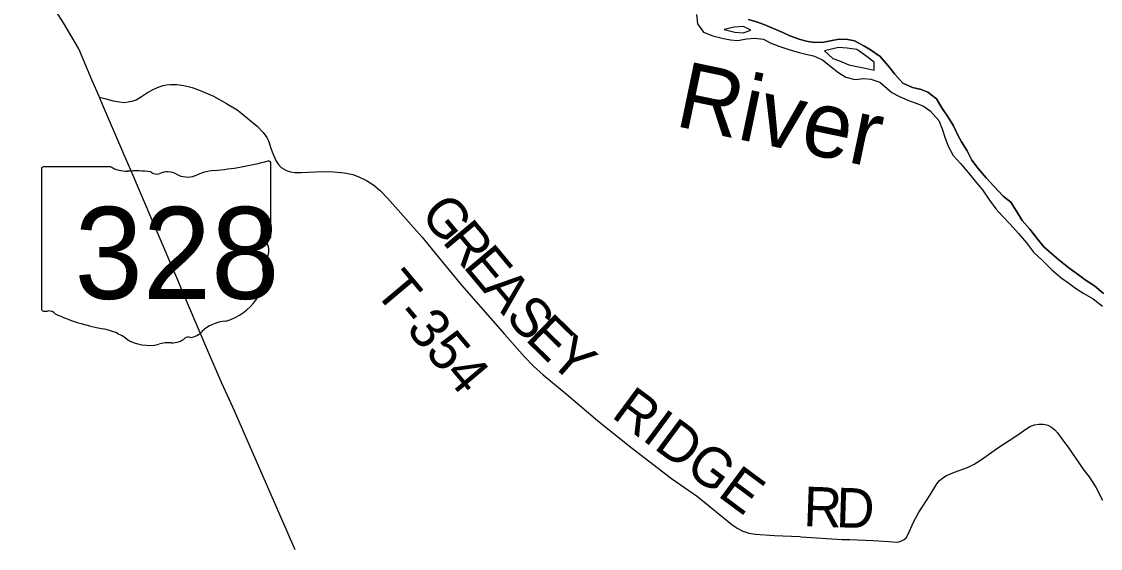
# Model space of a CAD drawing. Extents: x 0 to 34, y 0 to 22.
# Drawn here: x 4.986 to 6.535, y 19.405 to 20.161 of the extents above; entities that cross this region are included whole.
import ezdxf

# ---------------------------------------------------------------- set-up
doc = ezdxf.new("R2010")
doc.units = 0
for name, color, linetype in [('GM_X_Major_River', 7, 'Continuous'), ('GM_X_Major_River_Text', 7, 'Continuous'), ('GM_X_State_Location', 7, 'Continuous'), ('GM_X_State_Route', 7, 'Continuous'), ('GM_X_State_Shield', 7, 'Continuous'), ('GM_X_Township_Road', 7, 'Continuous'), ('GM_X_Township_Road_Text', 7, 'Continuous')]:
    doc.layers.add(name, color=color, linetype=linetype)

msp = doc.modelspace()

# ---------------------------------------------------------------- linework, layer by layer
at = {"layer": 'GM_X_Major_River'}
for p, q in [((5.9547, 20.1708), (5.9559, 20.1575)), ((5.9559, 20.1575), (5.9647, 20.1455)), ((6.0086, 20.1527), (5.9943, 20.1493)), ((6.0218, 20.1536), (6.0086, 20.1527)), ((6.0251, 20.152), (6.0218, 20.1536)), ((6.0328, 20.1484), (6.0251, 20.152)), ((6.0407, 20.1602), (6.0293, 20.1639)), ((6.0528, 20.1561), (6.0407, 20.1602)), ((6.0786, 20.145), (6.0528, 20.1561)), ((5.9647, 20.1455), (5.978, 20.1403)), ((5.978, 20.1403), (5.9936, 20.1366)), ((5.9936, 20.1366), (6.0034, 20.1344)), ((5.9943, 20.1493), (6.0098, 20.1455)), ((6.0034, 20.1344), (6.0137, 20.1338)), ((6.0098, 20.1455), (6.0215, 20.1445)), ((6.0137, 20.1338), (6.0269, 20.1362)), ((6.0215, 20.1445), (6.0328, 20.1484)), ((6.0269, 20.1362), (6.0378, 20.137)), ((6.0378, 20.137), (6.0507, 20.1353)), ((6.0507, 20.1353), (6.0606, 20.13)), ((6.0885, 20.1405), (6.0786, 20.145)), ((6.1022, 20.1357), (6.0885, 20.1405)), ((6.112, 20.1324), (6.1022, 20.1357)), ((6.1593, 20.1355), (6.1495, 20.1335)), ((6.1718, 20.1352), (6.1593, 20.1355)), ((6.1813, 20.133), (6.1718, 20.1352)), ((6.0606, 20.13), (6.0731, 20.1256)), ((6.0731, 20.1256), (6.0872, 20.1208)), ((6.0872, 20.1208), (6.102, 20.1164)), ((6.1242, 20.1306), (6.112, 20.1324)), ((6.1374, 20.1311), (6.1242, 20.1306)), ((6.1495, 20.1335), (6.1374, 20.1311)), ((6.1583, 20.1234), (6.1383, 20.119)), ((6.1383, 20.119), (6.1505, 20.1077)), ((6.1712, 20.1227), (6.1583, 20.1234)), ((6.1848, 20.1206), (6.1712, 20.1227)), ((6.195, 20.126), (6.1813, 20.133)), ((6.1977, 20.1116), (6.1848, 20.1206)), ((6.2045, 20.1204), (6.195, 20.126)), ((6.2182, 20.1106), (6.2045, 20.1204)), ((6.102, 20.1164), (6.1118, 20.1138)), ((6.1118, 20.1138), (6.1228, 20.1117)), ((6.1228, 20.1117), (6.1354, 20.1057)), ((6.1354, 20.1057), (6.1479, 20.096)), ((6.1505, 20.1077), (6.16, 20.1044)), ((6.16, 20.1044), (6.1733, 20.0985)), ((6.2099, 20.1026), (6.1977, 20.1116)), ((6.2304, 20.0967), (6.2182, 20.1106)), ((6.1479, 20.096), (6.159, 20.087)), ((6.1733, 20.0985), (6.1873, 20.0956)), ((6.1873, 20.0956), (6.1968, 20.0941)), ((6.1968, 20.0941), (6.2096, 20.0912)), ((6.2096, 20.0912), (6.2098, 20.0983)), ((6.2098, 20.0983), (6.2099, 20.1026)), ((6.2392, 20.0854), (6.2304, 20.0967)), ((6.159, 20.087), (6.1689, 20.081)), ((6.1689, 20.081), (6.1821, 20.0777)), ((6.1821, 20.0777), (6.195, 20.079)), ((6.195, 20.079), (6.2048, 20.0779)), ((6.2048, 20.0779), (6.2177, 20.0739)), ((6.2177, 20.0739), (6.2353, 20.0589)), ((6.251, 20.0723), (6.2392, 20.0854)), ((6.2647, 20.066), (6.251, 20.0723)), ((6.2353, 20.0589), (6.2452, 20.0537)), ((6.2772, 20.0634), (6.2647, 20.066)), ((6.2867, 20.0593), (6.2772, 20.0634)), ((6.2993, 20.05), (6.2867, 20.0593)), ((6.2452, 20.0537), (6.2588, 20.0477)), ((6.2588, 20.0477), (6.2698, 20.0437)), ((6.2698, 20.0437), (6.2805, 20.0392)), ((6.307, 20.0368), (6.2993, 20.05)), ((6.2805, 20.0392), (6.29, 20.0328)), ((6.29, 20.0328), (6.3026, 20.0189)), ((6.3162, 20.0236), (6.307, 20.0368)), ((6.3026, 20.0189), (6.308, 20.0057)), ((6.3235, 20.0112), (6.3162, 20.0236)), ((6.3292, 19.9987), (6.3235, 20.0112)), ((6.308, 20.0057), (6.3111, 19.9948)), ((6.3111, 19.9948), (6.3161, 19.9823)), ((6.335, 19.9885), (6.3292, 19.9987)), ((6.3161, 19.9823), (6.3231, 19.9687)), ((6.3431, 19.9753), (6.335, 19.9885)), ((6.3231, 19.9687), (6.3338, 19.9571)), ((6.35, 19.9618), (6.3431, 19.9753)), ((6.3338, 19.9571), (6.3445, 19.9443)), ((6.3592, 19.9501), (6.35, 19.9618)), ((6.3707, 19.9366), (6.3592, 19.9501)), ((6.3445, 19.9443), (6.3567, 19.9296)), ((6.3817, 19.9245), (6.3707, 19.9366)), ((6.3567, 19.9296), (6.3651, 19.9195)), ((6.3651, 19.9195), (6.3751, 19.9048)), ((6.3951, 19.9106), (6.3817, 19.9245)), ((6.3751, 19.9048), (6.3843, 19.892)), ((6.4058, 19.902), (6.3951, 19.9106)), ((6.4142, 19.8888), (6.4058, 19.902)), ((6.3843, 19.892), (6.3938, 19.8818)), ((6.4223, 19.8756), (6.4142, 19.8888)), ((6.3938, 19.8818), (6.4049, 19.8702)), ((6.433, 19.8629), (6.4223, 19.8756)), ((6.4049, 19.8702), (6.4171, 19.857)), ((6.4171, 19.857), (6.4286, 19.8435)), ((6.4433, 19.8501), (6.433, 19.8629)), ((6.4286, 19.8435), (6.4386, 19.8299)), ((6.4532, 19.8377), (6.4433, 19.8501)), ((6.4386, 19.8299), (6.4515, 19.8179)), ((6.4647, 19.8275), (6.4532, 19.8377)), ((6.475, 19.8193), (6.4647, 19.8275)), ((6.4515, 19.8179), (6.4645, 19.8052)), ((6.4894, 19.8077), (6.475, 19.8193)), ((6.4645, 19.8052), (6.4782, 19.7932)), ((6.4782, 19.7932), (6.4893, 19.7857)), ((6.5032, 19.7976), (6.4894, 19.8077)), ((6.5127, 19.7904), (6.5032, 19.7976)), ((6.4893, 19.7857), (6.4988, 19.7786)), ((6.4988, 19.7786), (6.5106, 19.7707)), ((6.526, 19.7819), (6.5127, 19.7904)), ((6.539, 19.771), (6.526, 19.7819)), ((6.5106, 19.7707), (6.5243, 19.7633)), ((6.5243, 19.7633), (6.5376, 19.7528))]:
    msp.add_line(p, q, dxfattribs=at)
for points in [[(5.9547, 20.1708), (5.9559, 20.1575), (5.9647, 20.1455), (5.978, 20.1403), (5.9936, 20.1366), (6.0034, 20.1344), (6.0137, 20.1338), (6.0269, 20.1362), (6.0378, 20.137), (6.0507, 20.1353), (6.0606, 20.13), (6.0731, 20.1256), (6.0872, 20.1208), (6.102, 20.1164), (6.1118, 20.1138), (6.1228, 20.1117), (6.1354, 20.1057), (6.1479, 20.096), (6.159, 20.087), (6.1689, 20.081), (6.1821, 20.0777), (6.195, 20.079), (6.2048, 20.0779), (6.2177, 20.0739), (6.2353, 20.0589), (6.2452, 20.0537), (6.2588, 20.0477), (6.2698, 20.0437), (6.2805, 20.0392), (6.29, 20.0328), (6.3026, 20.0189), (6.308, 20.0057), (6.3111, 19.9948)], [(6.0293, 20.1639), (6.0407, 20.1602), (6.0528, 20.1561), (6.0786, 20.145), (6.0885, 20.1405), (6.1022, 20.1357), (6.112, 20.1324), (6.1242, 20.1306), (6.1374, 20.1311), (6.1495, 20.1335), (6.1593, 20.1355), (6.1718, 20.1352), (6.1813, 20.133), (6.195, 20.126), (6.2045, 20.1204), (6.2182, 20.1106), (6.2304, 20.0967), (6.2392, 20.0854), (6.251, 20.0723), (6.2647, 20.066), (6.2772, 20.0634), (6.2867, 20.0593), (6.2993, 20.05), (6.307, 20.0368), (6.3162, 20.0236), (6.3235, 20.0112), (6.3292, 19.9987)], [(6.3111, 19.9948), (6.3161, 19.9823), (6.3231, 19.9687), (6.3338, 19.9571), (6.3445, 19.9443), (6.3567, 19.9296), (6.3651, 19.9195), (6.3751, 19.9048), (6.3843, 19.892), (6.3938, 19.8818), (6.4049, 19.8702), (6.4171, 19.857), (6.4286, 19.8435), (6.4386, 19.8299), (6.4515, 19.8179), (6.4645, 19.8052), (6.4782, 19.7932), (6.4893, 19.7857), (6.4988, 19.7786), (6.5106, 19.7707), (6.5243, 19.7633), (6.5376, 19.7528)], [(6.3292, 19.9987), (6.335, 19.9885), (6.3431, 19.9753), (6.35, 19.9618), (6.3592, 19.9501), (6.3707, 19.9366), (6.3817, 19.9245), (6.3951, 19.9106), (6.4058, 19.902), (6.4142, 19.8888), (6.4223, 19.8756), (6.433, 19.8629), (6.4433, 19.8501), (6.4532, 19.8377), (6.4647, 19.8275), (6.475, 19.8193), (6.4894, 19.8077), (6.5032, 19.7976), (6.5127, 19.7904), (6.526, 19.7819), (6.539, 19.771)]]:
    msp.add_lwpolyline(points, dxfattribs=at)
at = {"layer": 'GM_X_State_Route'}
msp.add_lwpolyline([(5.3784, 19.4034), (5.2915, 19.6027), (5.2735, 19.6423), (5.2559, 19.682), (5.2256, 19.7535), (5.2085, 19.7935), (5.1523, 19.925), (5.1459, 19.94), (5.1328, 19.9707), (5.1019, 20.042), (5.0975, 20.0523), (5.0868, 20.0773), (5.0679, 20.1215), (5.0462, 20.1588), (5.0349, 20.1759), (5.0224, 20.1908), (5.0031, 20.2056), (4.9759, 20.2251)], dxfattribs=at)
at = {"layer": 'GM_X_State_Shield'}
for p, q in [((5.0142, 19.9491), (5.0142, 19.749)), ((5.114, 19.9526), (5.0175, 19.9526)), ((5.3438, 19.8528), (5.3438, 19.9575)), ((5.3438, 19.8529), (5.3438, 19.8528))]:
    msp.add_line(p, q, dxfattribs=at)
for centre, major_axis, start_param, end_param in [((5.018, 19.9495), (0.00382, 0), 1.712693, 3.28349), ((5.137, 19.9758), (0.037, 0), 4.042523, 4.731795), ((5.2264, 20.2254), (0.3495, 0), 4.814394, 5.042369), ((5.3401, 19.9579), (0.00367, 0), 6.141152, 7.989035), ((5.1492, 19.8402), (0.133, 0), 1.404758, 1.657858), ((5.1794, 19.9506), (0.0107, 0), 3.836095, 5.185415), ((5.1951, 19.9274), (0.0222, 0), 0.950623, 2.079405), ((5.2238, 19.9592), (0.0267, 0), 4.081561, 5.145723), ((5.271, 19.8914), (0.0703, 0), 1.699011, 2.107814), ((5.3429, 19.8451), (0.00568, 0), 1.883978, 3.671073), ((5.3068, 19.8319), (0.0341, 0), 5.934695, 6.695948), ((5.3399, 19.8524), (0.00393, 0), 5.05454, 6.418171), ((5.3569, 19.809), (0.0248, 0), 2.387724, 3.262537), ((5.246, 19.7957), (0.0874, 0), 5.101752, 6.440018), ((5.018, 19.7486), (0.00385, 0), 3.00124, 4.508301), ((5.0186, 19.769), (0.0294, 0), 4.665946, 4.897461), ((5.0246, 19.7374), (0.0106, 0), 0.519207, 1.627899), ((5.1584, 19.9172), (0.2524, 0), 4.195997, 4.488961), ((5.0832, 19.6591), (0.079, 0), 0.823519, 1.323587), ((5.2222, 19.7296), (0.0282, 0), 4.937069, 5.64225), ((5.2828, 19.6928), (0.0479, 0), 1.647645, 2.488434), ((5.1686, 19.7365), (0.0501, 0), 4.026481, 4.996735), ((5.1976, 19.6673), (0.0412, 0), 1.495662, 1.94098), ((5.2012, 19.7215), (0.0267, 0), 4.691044, 5.507374), ((5.2254, 19.7021), (0.00752, 0), 1.147584, 2.315152)]:
    msp.add_ellipse(centre, major_axis=major_axis, ratio=0.8, start_param=start_param, end_param=end_param, dxfattribs=at)
at = {"layer": 'GM_X_Township_Road'}
for points in [[(5.0975, 20.0523), (5.1055, 20.0502), (5.1087, 20.0493), (5.1174, 20.047), (5.1265, 20.0454), (5.1327, 20.0449), (5.1387, 20.0454), (5.1447, 20.0465), (5.1504, 20.0487), (5.158, 20.0534), (5.1664, 20.0592), (5.1757, 20.064), (5.1831, 20.0671), (5.1891, 20.0691), (5.1939, 20.0701), (5.1994, 20.0707), (5.2088, 20.0707), (5.2186, 20.0692), (5.2306, 20.0661), (5.2447, 20.0609), (5.2613, 20.0538), (5.2801, 20.0433), (5.2954, 20.034), (5.3022, 20.029), (5.3238, 20.0106), (5.3324, 20.0018), (5.338, 19.9946), (5.3403, 19.9899), (5.3443, 19.9779), (5.3463, 19.9715), (5.3511, 19.9607), (5.3545, 19.9556), (5.3586, 19.9515), (5.366, 19.9473), (5.3719, 19.9453), (5.378, 19.9445), (5.3873, 19.9444), (5.4183, 19.9458), (5.4338, 19.9453), (5.4492, 19.9437), (5.4613, 19.9413), (5.47, 19.9382), (5.4811, 19.9327), (5.4915, 19.9261), (5.5009, 19.9182), (5.5112, 19.9076), (5.5602, 19.8523), (5.584, 19.8236), (5.6174, 19.7826), (5.6789, 19.7127), (5.7078, 19.6802), (5.7207, 19.6667), (5.7346, 19.6543), (5.7676, 19.6268), (5.8127, 19.5889), (5.8609, 19.5499), (5.9186, 19.5055), (5.9559, 19.4798), (6.0052, 19.4395), (6.0129, 19.4342), (6.0211, 19.4299), (6.03, 19.4271), (6.0392, 19.4255), (6.0667, 19.4238), (6.1031, 19.4222), (6.1051, 19.422)], [(6.1051, 19.422), (6.164, 19.4183), (6.1746, 19.4182), (6.2082, 19.4166), (6.2308, 19.415), (6.242, 19.4144), (6.2452, 19.4147), (6.2479, 19.4155), (6.253, 19.418), (6.2555, 19.4205), (6.2586, 19.4258), (6.266, 19.4427), (6.2736, 19.4561), (6.2901, 19.4821), (6.2998, 19.4979), (6.3036, 19.5027), (6.3083, 19.5067), (6.3137, 19.5099), (6.325, 19.5144), (6.3435, 19.5215), (6.3532, 19.5261), (6.3636, 19.5326), (6.3885, 19.5503), (6.4119, 19.5653), (6.4287, 19.5774), (6.4341, 19.5805), (6.44, 19.5824), (6.4461, 19.5834), (6.4523, 19.5836), (6.4554, 19.5832), (6.459, 19.582), (6.4612, 19.5811), (6.4644, 19.5793), (6.469, 19.5754), (6.4728, 19.571), (6.4843, 19.5554), (6.4866, 19.5522)], [(6.4866, 19.5522), (6.5109, 19.5174), (6.5182, 19.5078), (6.5281, 19.4933), (6.5374, 19.4745)]]:
    msp.add_lwpolyline(points, dxfattribs=at)

# ---------------------------------------------------------------- texts
at = {"layer": 'GM_X_Major_River_Text'}
msp.add_text('River', height=0.09469, rotation=348.1697, dxfattribs=at).set_placement((5.9216, 20.0115))
at = {"layer": 'GM_X_State_Location'}
for s in ['s', 'r']:
    msp.add_text(s, height=0.000189, dxfattribs=at).set_placement((5.1753, 19.8357))
msp.add_text('328', height=0.000189, rotation=0, dxfattribs=at).set_placement((5.1084, 19.822))
at = {"layer": 'GM_X_State_Shield'}
msp.add_text('328', height=0.13184, dxfattribs=at).set_placement((5.0618, 19.7631))
at = {"layer": 'GM_X_Township_Road_Text'}
for s, height, rotation, p in [('G', 0.0568, 309.8569, (5.5564, 19.8835)), ('R', 0.0568, 309.857, (5.5885, 19.8451)), ('E', 0.0568, 309.86, (5.6184, 19.8093)), ('T-354', 0.05682, 310.0206, (5.4904, 19.7741)), ('A', 0.0568, 309.8808, (5.6456, 19.7767)), ('S', 0.0568, 311.4397, (5.6788, 19.737)), ('E', 0.0568, 315.7128, (5.7074, 19.7049)), ('Y', 0.0568, 318.7749, (5.7402, 19.673)), ('RIDGE', 0.05682, 323.4446, (5.8309, 19.5946)), ('R', 0.0568, 357.9348, (6.1076, 19.4373)), ('D', 0.0568, 358.1608, (6.1545, 19.4357))]:
    msp.add_text(s, height=height, rotation=rotation, dxfattribs=at).set_placement(p)

doc.saveas('drawing.dxf')
